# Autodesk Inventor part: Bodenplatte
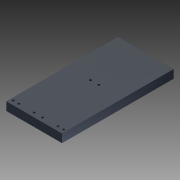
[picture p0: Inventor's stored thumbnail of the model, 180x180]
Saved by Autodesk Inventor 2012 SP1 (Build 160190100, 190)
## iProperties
Created: 2012-10
Part Number: Bodenplatte
Material: Default
Document SubType Name: Modeling
Designer: Dominic Mähling
Density: 1 g/cm^3
Author: Dominic Mähling
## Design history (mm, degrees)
derived "Funkenstrecke master.ipt"
feature "Bodenplatte::Funkenstrecke master.ipt" dims "d0" = 10
tag "Bezeichnung1"
node "Volumenkörper1"
